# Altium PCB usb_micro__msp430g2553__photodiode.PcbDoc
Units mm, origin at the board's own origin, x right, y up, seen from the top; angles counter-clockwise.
Board outline 56 x 30 mm, 2 copper layers (Top, Bottom), stack 0 mm thick; 25 components, 16 nets, 113 pads, 34 vias.
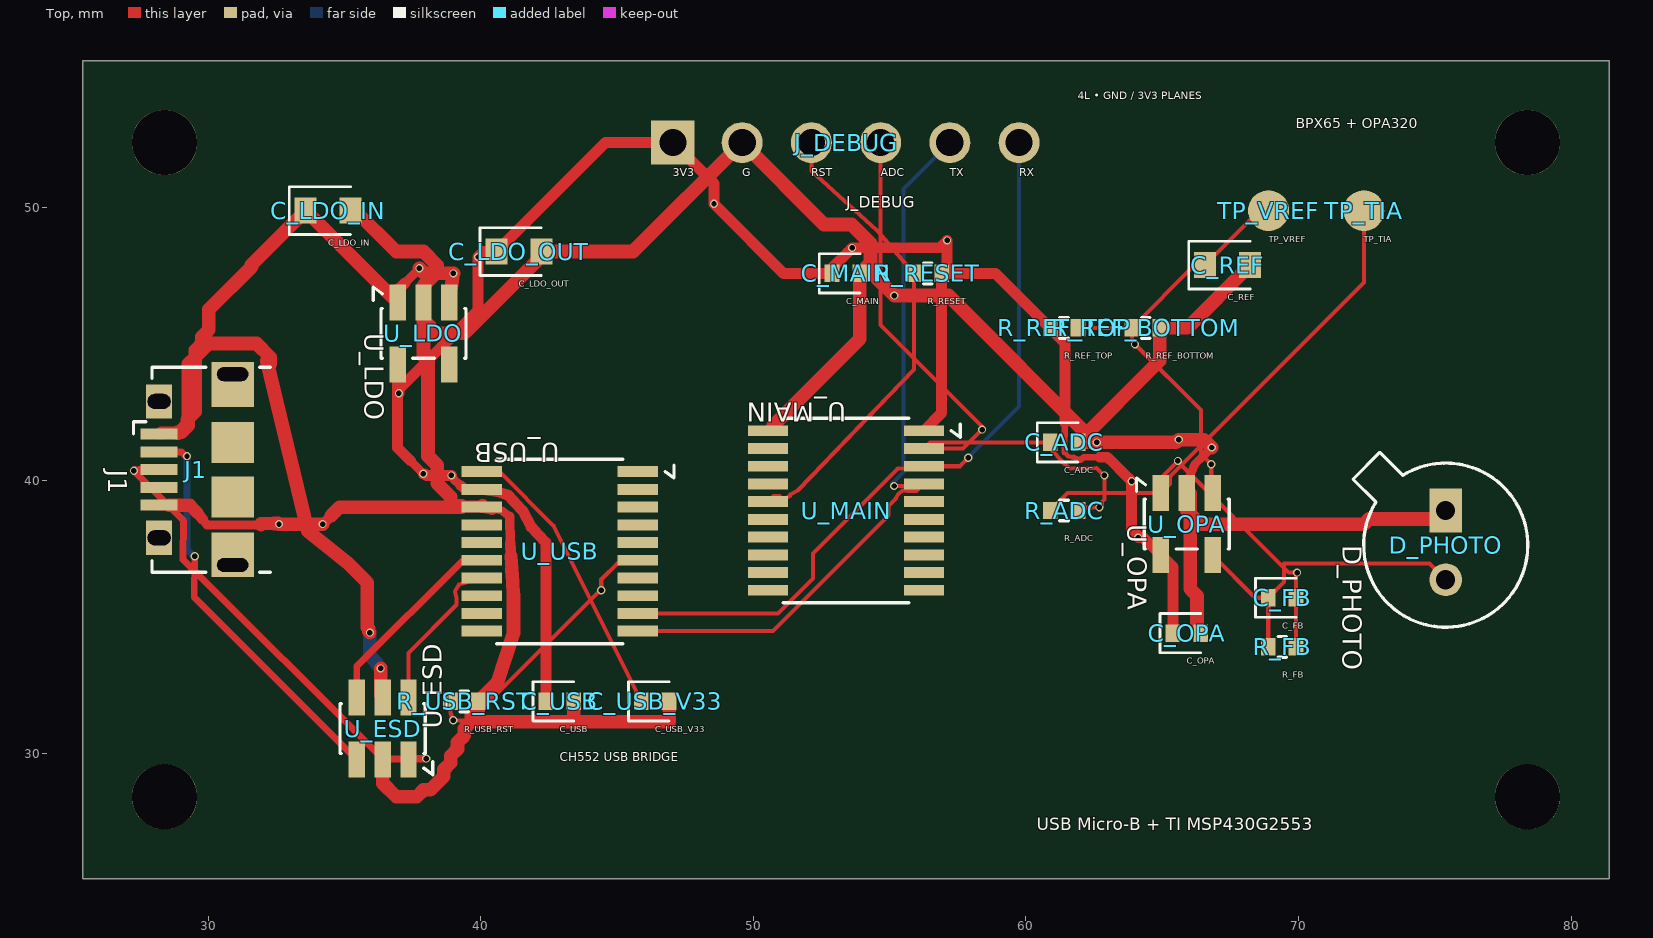
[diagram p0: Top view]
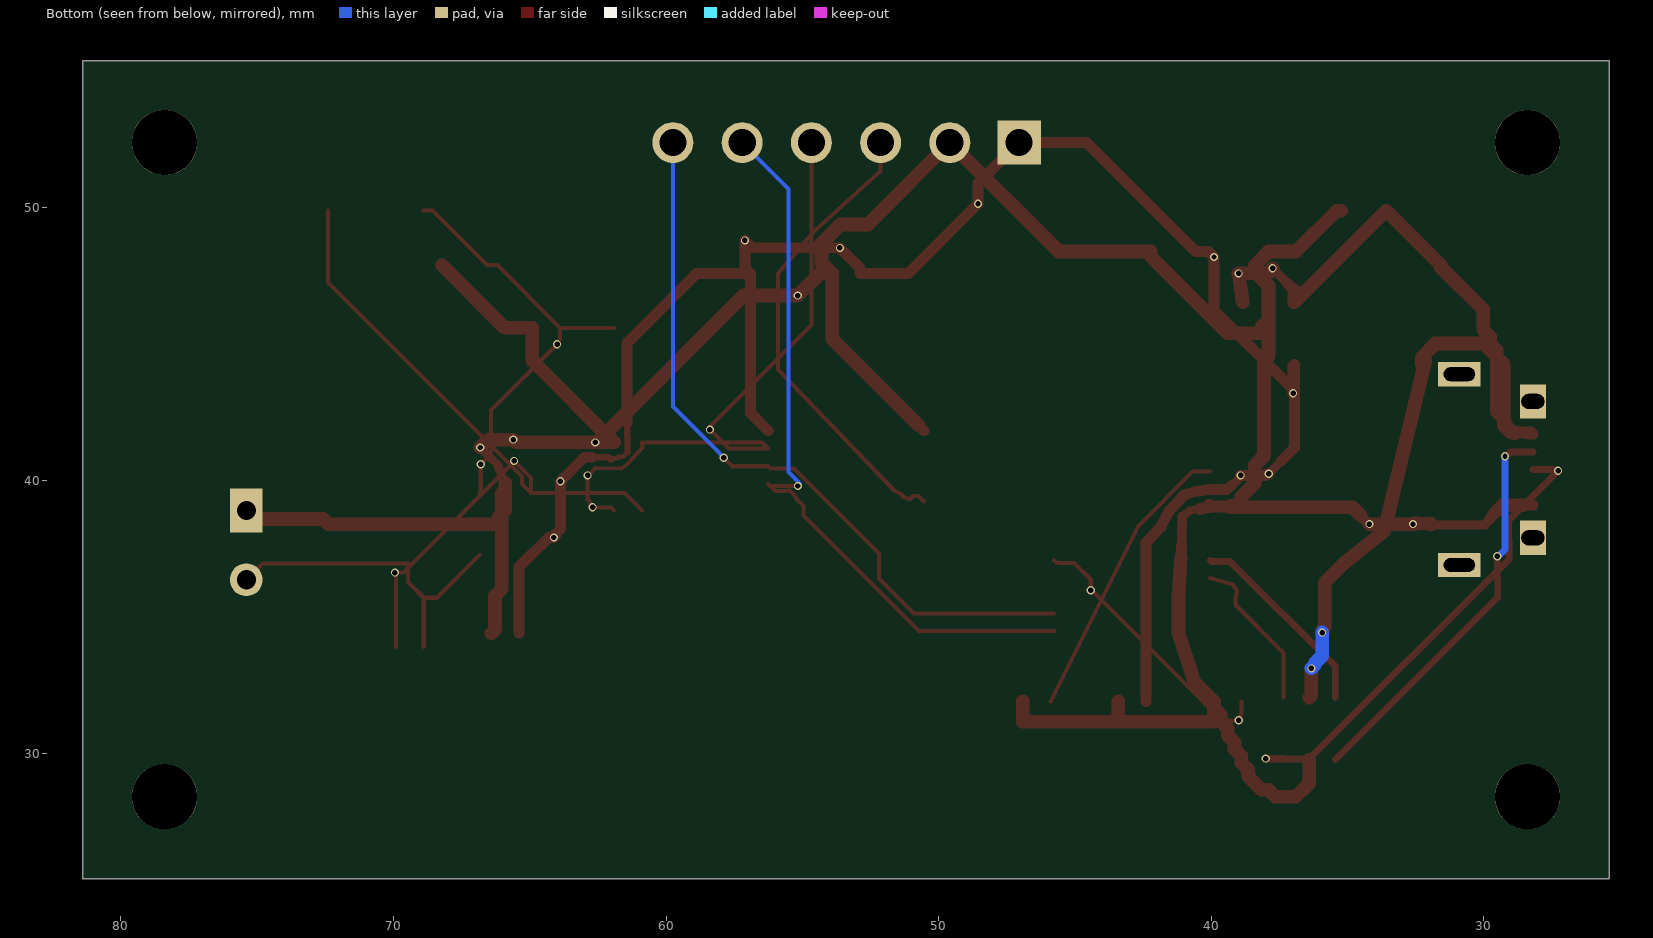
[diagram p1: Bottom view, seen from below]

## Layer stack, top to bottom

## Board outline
25.4,55.4 81.4,55.4 81.4,25.4 25.4,25.4

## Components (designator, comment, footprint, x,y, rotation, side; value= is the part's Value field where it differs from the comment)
C_ADC "" TSCIRCUIT-1.5600x0.6400mm 61.4,41.4 r0 top
C_FB "" TSCIRCUIT-1.5600x0.6400mm 69.4,35.7 r0 top
C_LDO_IN "" TSCIRCUIT-2.4500x0.9500mm 34.4,49.9 r0 top
C_LDO_OUT "" TSCIRCUIT-2.4500x0.9500mm 41.4,48.4 r0 top
C_MAIN "" TSCIRCUIT-1.5600x0.6400mm 53.4,47.6 r0 top
C_OPA "" TSCIRCUIT-1.5600x0.6400mm 65.9,34.4 r0 top
C_REF "" TSCIRCUIT-2.4500x0.9500mm 67.4,47.9 r0 top
C_USB "" TSCIRCUIT-1.5600x0.6400mm 42.9,31.9 r0 top
C_USB_V33 "" TSCIRCUIT-1.5600x0.6400mm 46.4,31.9 r0 top
D_PHOTO "" TSCIRCUIT-1.2000x3.9400mm 75.4,37.73 r270 top
J1 "" TSCIRCUIT-4.1500x7.8900mm 29.6,40.4 r270 top
J_DEBUG "" TSCIRCUIT-14.2000x1.5000mm 53.4,52.4 r0 top
R_ADC "" TSCIRCUIT-1.5600x0.6400mm 61.4,38.9 r0 top
R_FB "" TSCIRCUIT-1.5600x0.6400mm 69.4,33.9 r0 top
R_REF_BOTTOM "" TSCIRCUIT-1.5600x0.6400mm 64.4,45.6 r0 top
R_REF_TOP "" TSCIRCUIT-1.5600x0.6400mm 61.4,45.6 r0 top
R_RESET "" TSCIRCUIT-1.5600x0.6400mm 56.4,47.6 r0 top
R_USB_RST "" TSCIRCUIT-1.5600x0.6400mm 39.4,31.9 r0 top
TP_TIA "" TSCIRCUIT-1.5000x1.5000mm 72.4,49.9 r0 top
TP_VREF "" TSCIRCUIT-1.5000x1.5000mm 68.9,49.9 r0 top
U_ESD "" TSCIRCUIT-2.5000x3.6000mm#1 36.4,30.9 r90 top
U_LDO "" TSCIRCUIT-2.5000x3.6000mm#2 37.9,45.4 r270 top
U_MAIN "" TSCIRCUIT-7.2000x6.2500mm 53.4,38.9 r180 top
U_OPA "" TSCIRCUIT-2.5000x3.6000mm#2 65.9,38.4 r270 top
U_USB "" TSCIRCUIT-7.2000x6.2500mm 42.9,37.4 r180 top

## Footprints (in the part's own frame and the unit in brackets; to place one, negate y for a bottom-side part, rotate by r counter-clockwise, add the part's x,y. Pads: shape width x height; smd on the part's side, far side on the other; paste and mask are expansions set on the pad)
TSCIRCUIT-1.2000x3.9400mm [mm]
  rect 1.6x1.2 hole 0.7: 1(-1.17,0)
  round 1.2 hole 0.7: 2(1.37,0)
  silkscreen extent -3.3,-3.4 3.11,3.01
TSCIRCUIT-1.5000x1.5000mm [mm]
  round 1.5 smd: 1(0,0)
TSCIRCUIT-1.5600x0.6400mm [mm]
  rect 0.54x0.64 smd: 1(-0.51,0) 2(0.51,0)
  silkscreen extent -0.98,-0.72 0.51,0.72
TSCIRCUIT-2.4500x0.9500mm [mm]
  rect 0.8x0.95 smd: 1(-0.825,0) 2(0.825,0)
  silkscreen extent -1.43,-0.87 0.82,0.87
TSCIRCUIT-2.5000x3.6000mm#1 [mm]
  rect 1.325x0.6 smd: 1(-1.137,-0.95) 2(-1.137,0) 3(-1.137,0.95) 4(1.138,0.95) 5(1.138,0) 6(1.138,-0.95)
  silkscreen extent -1.69,-1.84 0.91,1.56
TSCIRCUIT-2.5000x3.6000mm#2 [mm]
  rect 1.325x0.6 smd: 1(-1.137,-0.95) 2(-1.137,0) 3(-1.137,0.95) 4(1.138,0.95) 5(1.138,-0.95)
  silkscreen extent -1.69,-1.84 0.91,1.56
TSCIRCUIT-4.1500x7.8900mm [mm]
  rect 0.89x1.55 hole 0.5 slot 1.15 at 90 deg: 1(-3.5,1.3) 1(3.5,1.3)
  rect 1.45x1.55 smd: 1(-3.025,1.3) 1(3.025,1.3)
  rect 1.25x0.95 hole 0.55 slot 0.85 at 90 deg: 1(-2.5,-1.4) 1(2.5,-1.4)
  rect 0.4x1.35 smd: 1(-1.3,-1.4) 2(-0.65,-1.4) 3(0,-1.4) 4(0.65,-1.4) 5(1.3,-1.4)
  rect 1.5x1.55 smd: 1(-1,1.3) 1(1,1.3)
  silkscreen extent -3.76,-2.34 3.76,2.69
TSCIRCUIT-7.2000x6.2500mm [mm]
  rect 1.475x0.4 smd: 1(-2.863,-2.925) 2(-2.863,-2.275) 3(-2.863,-1.625) 4(-2.863,-0.975) 5(-2.863,-0.325) 6(-2.863,0.325) 7(-2.863,0.975) 8(-2.863,1.625) 9(-2.863,2.275) 10(-2.863,2.925) 11(2.862,2.925) 12(2.862,2.275) 13(2.862,1.625) 14(2.862,0.975) 15(2.862,0.325) 16(2.862,-0.325) 17(2.862,-0.975) 18(2.862,-1.625) 19(2.862,-2.275) 20(2.862,-2.925)
  silkscreen extent -4.19,-3.38 2.31,3.39
TSCIRCUIT-14.2000x1.5000mm [mm]
  rect 1.6x1.6 hole 1: 1(-6.35,0)
  round 1.5 hole 1: 2(-3.81,0) 3(-1.27,0) 4(1.27,0) 5(3.81,0) 6(6.35,0)

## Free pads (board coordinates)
  round 2.4 hole 2.4 unplated: NPTH-1(28.4,28.4) NPTH-2(78.4,52.4) NPTH-3(78.4,28.4) NPTH-4(28.4,52.4)

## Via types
v1: diameter 0.3, hole 0.2, Top to Bottom, 34 vias

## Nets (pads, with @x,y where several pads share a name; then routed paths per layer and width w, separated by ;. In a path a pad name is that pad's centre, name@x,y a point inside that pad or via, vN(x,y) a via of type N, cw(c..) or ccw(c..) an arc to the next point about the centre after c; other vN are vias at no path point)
ADC_IN: C_ADC.1 J_DEBUG.4 R_ADC.2 U_MAIN.2 | length 24
  Top w0.15: J_DEBUG.4 54.67,45.7 58.438,41.932 58.438,41.916 v1(58.391,41.869) 57.697,41.175 U_MAIN.2 56.487,41.4 C_ADC.1 60.87,41.207 61.411,40.606 61.631,40.445 62.587,40.465 62.809,40.243 62.824,40.243 v1(62.881,40.186) 62.881,39.308 62.796,39.223 62.796,39.117 v1(62.696,39.017) 62.027,39.017 R_ADC.2
GND: C_ADC.2 C_LDO_IN.2 C_LDO_OUT.2 C_MAIN.2 C_OPA.2 C_REF.2 C_USB.2 C_USB_V33.2 D_PHOTO.1 J1.5 J_DEBUG.2 R_REF_BOTTOM.2 R_USB_RST.2 U_ESD.2 U_LDO.2 U_MAIN.20 U_OPA.2 U_USB.18 | length 127.5
  Top w0.312: U_USB.18@40.406,38.963 40.775,38.9 41.056,38.681 ; U_OPA.2@65.9,39.921 66.053,40.264 66.206,40.607 66.513,40.91 v1(66.819,41.212)
  Top w0.325: 29.797,38.579 29.963,38.369 31.935,38.369
  Top w0.35: 41.056,38.681 41.083,37.7
  Top w0.375: v1(34.2,38.4) 34.512,38.713
  Top w0.4: J1.5 J1.5@28.573,39.1 ; 29.631,38.789 29.797,38.579 ; U_USB.18@39.3,39.025 39.564,39.025 U_USB.18 U_USB.18@40.067,39.054 ; U_USB.18@39.3,39.067 U_USB.18@40.067,39.067 ; 41.083,37.7 41.113,37.225 ; U_MAIN.20 50.737,42.025
  Top w0.437: U_USB.18 U_USB.18@40.406,38.963
  Top w0.45: 29.32,39.1 29.631,38.789
  Top w0.475: 31.935,38.369 31.935,38.426 32.42,38.426 ; 41.113,37.225 41.142,36.75
  Top w0.5: J1.5@28.573,39.1 28.946,39.1 29.32,39.1 ; 32.42,38.426 32.574,38.426 v1(32.6,38.4) 33.099,38.4 33.599,38.4 34.098,38.4 v1(34.2,38.4) ; 34.512,38.713 34.825,39.025 35.299,39.025 35.773,39.025 36.247,39.025 36.72,39.025 37.194,39.025 37.668,39.025 38.142,39.025 38.616,39.025 39.09,39.025 U_USB.18@39.3,39.025 ; C_LDO_IN.2 35.4,49.9 36.9,48.4 37.9,48.4 38.4,47.9 38.4,47.65 37.9,47.15 U_LDO.2 ; U_ESD.2 36.4,28.9 36.9,28.4 37.65,28.4 37.9,28.65 38.15,28.65 38.65,29.15 38.65,29.4 38.9,29.65 38.9,29.9 39.15,30.15 39.15,30.4 39.4,30.65 39.4,30.9 39.65,31.15 39.65,31.4 39.9,31.65 39.9,31.9 R_USB_RST.2 ; U_USB.18@39.3,39.067 39.067,39.067 38.9,39.233 38.9,39.4 38.4,39.9 38.4,40.567 38.067,40.9 38.067,44.4 37.901,44.566 37.901,44.598 37.901,45.083 37.901,45.568 37.9,46.053 U_LDO.2 ; U_USB.18@40.067,39.054 U_USB.18@40.067,39.067 ; 41.142,36.75 41.171,36.275 41.2,35.8 41.2,35.333 41.2,34.867 41.2,34.4 40.615,32.596 40.262,32.248 R_USB_RST.2 ; C_USB_V33.2 46.91,31.15 43.41,31.15 ; 50.738,42.025 53.91,45.197 C_MAIN.2 ; U_OPA.2@65.9,39.921 U_OPA.2 ; C_OPA.2 66.4,34.4 66.275,34.525 66.275,35.775 66.025,36.025 66.025,39.525 65.912,39.525 U_OPA.2 ; v1(66.819,41.212) 66.762,41.269 66.759,41.269 66.525,41.503 66.066,41.503 v1(65.607,41.503) 65.504,41.4 C_ADC.2 ; C_REF.2 65.925,45.6 R_REF_BOTTOM.2 64.91,44.4 C_ADC.2 ; D_PHOTO.1 75.089,38.589 74.611,38.589 74.134,38.589 73.657,38.589 73.18,38.589 72.703,38.589 72.589,38.589 72.4,38.4 66.15,38.4 66.15,38.65 65.9,38.9 U_OPA.2 ; U_LDO.2 37.9,45.9 38.15,45.65 38.15,45.4 39.4,45.4 42.225,48.225 C_LDO_OUT.2 45.59,48.4 J_DEBUG.2 52.595,49.395 53.605,49.395 54.1,48.9 54.3,48.7 54.3,48.1 54.3,47.99 C_MAIN.2 ; R_USB_RST.2 39.91,31.15 43.41,31.15 ; 43.41,31.15 C_USB.2 43.41,31.15 ; C_MAIN.2 54.353,47.6 v1(55.167,46.786) 57.159,46.786 62.545,41.4 v1(62.6,41.4) C_ADC.2
MAIN_RESET: J_DEBUG.3 R_RESET.1 U_MAIN.16 | length 17.4
  Top w0.15: U_MAIN.16 50.738,39.426 50.953,39.426 51.061,39.304 51.343,39.428 51.343,39.478 51.649,39.648 55.89,44.079 R_RESET.1 54.715,48.97 54.518,49.187 52.13,51.36 J_DEBUG.3
PD_SUM: C_FB.1 D_PHOTO.2 R_FB.1 U_OPA.4 | length 12.2
  Top w0.15: U_OPA.4 68.412,35.7 C_FB.1 ; R_FB.1 C_FB.1 ; D_PHOTO.2 74.799,36.961 69.465,36.962 69.465,36.275 C_FB.1
TIA_OUT: C_FB.2 R_ADC.1 R_FB.2 TP_TIA.1 U_OPA.1 | length 28
  Top w0.15: R_ADC.1 61.527,39.538 U_OPA.1 ; R_FB.2 C_FB.2 69.91,36.45 69.91,36.584 v1(69.95,36.622) 69.642,36.624 65.589,40.676 65.589,40.709 v1(65.576,40.722) 64.95,40.096 U_OPA.1 ; TP_TIA.1 72.399,47.266 65.278,40.153 65.283,39.87 U_OPA.1
UART_MAIN_RX: J_DEBUG.6 U_MAIN.3 U_USB.9 | length 27.4
  Top w0.15: U_USB.9 50.905,35.125 52.185,36.404 52.185,37.323 55.299,40.438 56.175,40.438 U_MAIN.3 57.576,40.525 v1(57.885,40.834)
  Bottom w0.15: v1(57.885,40.834) 58.043,40.992 58.043,41.013 59.75,42.72 J_DEBUG.6
UART_MAIN_TX: J_DEBUG.5 U_MAIN.4 U_USB.10 | length 27.6
  Top w0.15: U_USB.10 50.715,34.475 54.952,38.712 54.952,39.069 55.229,39.347 55.32,39.507 55.491,39.638 55.648,39.615 55.992,39.615 U_MAIN.4 56.188,39.8 v1(55.163,39.8)
  Bottom w0.15: v1(55.163,39.8) 55.081,39.882 55.512,40.314 55.512,40.397 55.512,50.702 J_DEBUG.5
USB_BRIDGE_RESET: R_USB_RST.1 U_USB.6 | length 10.2
  Top w0.15: R_USB_RST.1 38.89,31.457 38.93,31.417 38.93,31.27 v1(38.995,31.205) 39.604,31.2 44.303,35.899 44.343,35.899 v1(44.421,35.977) 44.421,36.366 45.028,36.973 45.66,36.973 U_USB.6
USB_BRIDGE_V33: C_USB_V33.1 U_USB.20 | length 10.7
  Top w0.15: U_USB.20 40.681,40.325 42.684,38.322 C_USB_V33.1
USB_DM_MCU: U_ESD.4 U_USB.15 | length 7.3
  Top w0.25: U_ESD.4 35.45,33.174 39.306,37.03 39.993,37.03 U_USB.15
USB_DM_PORT: J1.2 U_ESD.3 | length 14.8
  Top w0.25: J1.2 29.024,41.05 29.148,40.926 29.187,40.926 v1(29.224,40.889) ; v1(29.506,37.221) 29.489,35.723 U_ESD.3
  Bottom w0.25: v1(29.224,40.889) 29.224,37.469 29.456,37.237 v1(29.506,37.221)
USB_DP_MCU: U_ESD.6 U_USB.14 | length 5.8
  Top w0.15: U_ESD.6 37.35,33.679 39.112,35.443 39.108,35.693 39.054,35.931 39.208,36.194 U_USB.14
USB_DP_PORT: J1.3 U_ESD.1 | length 17.6
  Top w0.25: J1.3 27.464,40.4 27.454,40.39 27.309,40.39 v1(27.275,40.356) 29.097,38.534 29.08,37.095 36.421,29.787 37.812,29.787 37.987,29.787 v1(38,29.8) 37.388,29.8 U_ESD.1
VBUS5: C_LDO_IN.1 J1.1@28.2,41.7 U_ESD.5 U_LDO.1 U_LDO.3 | length 40.7
  Top w0.325: 37.217,47.243 37.484,47.515 v1(37.752,47.787)
  Top w0.4: J1.1@28.875,41.733 28.4,41.733 28.367,41.7 28.2,41.7 28.275,41.775 J1.1@28.875,41.775 ; U_LDO.1@36.95,46.971 37.217,47.243
  Top w0.5: 28.875,41.733 28.9,41.733 29.233,42.067 29.233,42.233 29.525,42.525 29.525,44.525 ; 28.875,41.775 29.025,41.775 29.275,42.025 29.275,44.275 29.525,44.525 ; v1(35.935,34.423) 35.894,34.464 35.894,34.557 35.838,34.613 35.838,35.024 35.838,35.435 35.838,35.846 35.838,36.257 35.488,36.606 35.139,36.955 33.65,38.15 32.15,44.4 32.275,44.275 32.275,44.525 31.775,45.025 30.025,45.025 29.525,44.525 ; v1(36.328,33.107) 36.328,32.608 36.328,32.109 U_ESD.5 ; U_LDO.1@36.95,46.971 U_LDO.1 33.587,49.9 C_LDO_IN.1 33.244,49.569 32.913,49.238 32.582,48.907 32.251,48.576 31.92,48.245 31.589,47.914 31.589,47.839 30.025,46.275 30.025,45.525 29.775,45.275 29.775,45.025 29.525,44.775 29.525,44.525 ; v1(37.752,47.787) 37.938,47.6 v1(39,47.6) U_LDO.3
  Bottom w0.5: v1(35.935,34.423) 35.935,33.993 35.935,33.562 36.208,33.289 36.208,33.227 v1(36.328,33.107)
VCC_3V3: C_LDO_OUT.1 C_MAIN.1 C_OPA.1 C_USB.1 J_DEBUG.1 R_REF_TOP.1 R_RESET.2 U_LDO.5 U_MAIN.1 U_OPA.5 U_USB.19 | length 71.3
  Top w0.175: 61.419,41.033 61.559,40.893 61.751,40.846
  Top w0.2: 61.751,40.846 62.01,40.771
  Top w0.225: 61.419,41.033 61.421,41.398 61.423,41.763
  Top w0.238: 61.423,41.763 61.425,42.128
  Top w0.25: 62.01,40.771 62.134,40.854 62.42,40.854 62.706,40.854
  Top w0.312: 37.422,40.725 37.658,40.486 v1(37.894,40.247) ; v1(38.926,40.187) 39.05,40 39.244,39.837
  Top w0.375: 39.244,39.837 U_USB.19@39.438,39.675
  Top w0.387: 62.706,40.854 62.992,40.854 63.254,40.592 63.516,40.33
  Top w0.4: 37.422,40.725 37.186,40.964 36.95,41.203 36.95,41.585 36.95,41.968 36.95,42.35 36.95,42.733 36.95,43.115 36.95,43.498 36.95,43.88 U_LDO.5 37,44.212 v1(37,43.2) 37.005,43.205 37.005,43.348 39.9,46.242 v1(39.9,48.2) 39.905,48.205 39.906,48.205 40.102,48.4 C_LDO_OUT.1 44.575,52.4 J_DEBUG.1 48.557,50.893 v1(48.557,50.154) 48.657,50.054 51.111,47.6 C_MAIN.1 52.89,47.791 53.462,48.363 53.462,48.372 v1(53.624,48.534) 56.837,48.538 57.042,48.743 57.045,48.743 v1(57.109,48.807) 57.109,47.799 R_RESET.2 ; v1(37.894,40.247) 37.909,40.244 37.951,40.244 38.007,40.187 38.314,40.187 38.62,40.187 v1(38.926,40.187) ; U_USB.19@39.438,39.675 39.738,39.675 U_USB.19 40.6,39.6 41,39.467 41.539,38.898 41.851,38.302 42.12,38.011 42.39,37.719 42.39,37.331 42.39,36.944 42.39,36.556 42.39,36.168 42.39,35.78 42.39,35.392 42.39,35.004 42.39,34.616 42.39,34.228 42.39,33.84 42.39,33.452 42.39,33.064 42.39,32.676 42.39,32.288 C_USB.1 ; U_MAIN.1 56.91,42.473 R_RESET.2 ; 61.425,42.128 61.427,42.493 61.429,42.859 61.43,43.224 61.432,43.589 61.434,43.954 61.436,44.319 61.438,44.685 61.44,45.05 61.165,45.325 R_REF_TOP.1 58.89,47.6 R_RESET.2 ; 63.516,40.33 63.778,40.068 v1(63.875,39.971) 63.875,39.621 63.875,39.271 63.875,38.921 63.875,38.571 63.875,38.22 64.05,38.046 64.05,37.976 v1(64.115,37.911) 64.301,37.911 64.517,37.695 64.734,37.479 U_OPA.5 65.39,36.822 C_OPA.1
VREF_0V5: C_REF.1 R_REF_BOTTOM.1 R_REF_TOP.2 TP_VREF.1 U_OPA.3 | length 16.1
  Top w0.15: R_REF_TOP.2 R_REF_BOTTOM.1 ; U_OPA.3 66.8,39.587 v1(66.8,40.6) 66.686,40.714 66.418,40.982 66.418,41.101 66.418,42.582 v1(64,45) 63.941,45.059 63.941,45.121 63.89,45.172 R_REF_BOTTOM.1 ; TP_VREF.1 68.575,49.9 C_REF.1 66.19,47.9 R_REF_BOTTOM.1
pads on no net: J1.1@28.2,37.9 J1.1@28.2,42.9 J1.1@30.9,36.9 J1.1@30.9,37.375 J1.1@30.9,39.4 J1.1@30.9,41.4 J1.1@30.9,43.9 J1.1@30.9,43.425 J1.4 U_LDO.4 U_MAIN.5 U_MAIN.6 U_MAIN.7 U_MAIN.8 U_MAIN.9 U_MAIN.10 U_MAIN.11 U_MAIN.12 U_MAIN.13 U_MAIN.14 U_MAIN.15 U_MAIN.17 U_MAIN.18 U_MAIN.19 U_USB.1 U_USB.2 U_USB.3 U_USB.4 U_USB.5 U_USB.7 U_USB.8 U_USB.11 U_USB.12 U_USB.13 U_USB.16 U_USB.17

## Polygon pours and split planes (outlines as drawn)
GND on Mid1 (solid): 81.1,55.1 25.7,55.1 25.7,25.7 81.1,25.7
VCC_3V3 on Mid2 (solid): 81.1,55.1 25.7,55.1 25.7,25.7 81.1,25.7

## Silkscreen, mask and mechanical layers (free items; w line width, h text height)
Top Overlay:
  text "4L • GND / 3V3 PLANES" at 61.9,53.9 h0.48
  text "BPX65 + OPA320" at 69.9,52.8 h0.65
  text "CH552 USB BRIDGE" at 42.9,29.6 h0.55
  text "USB Micro-B + TI MSP430G2553" at 60.4,27 h0.78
